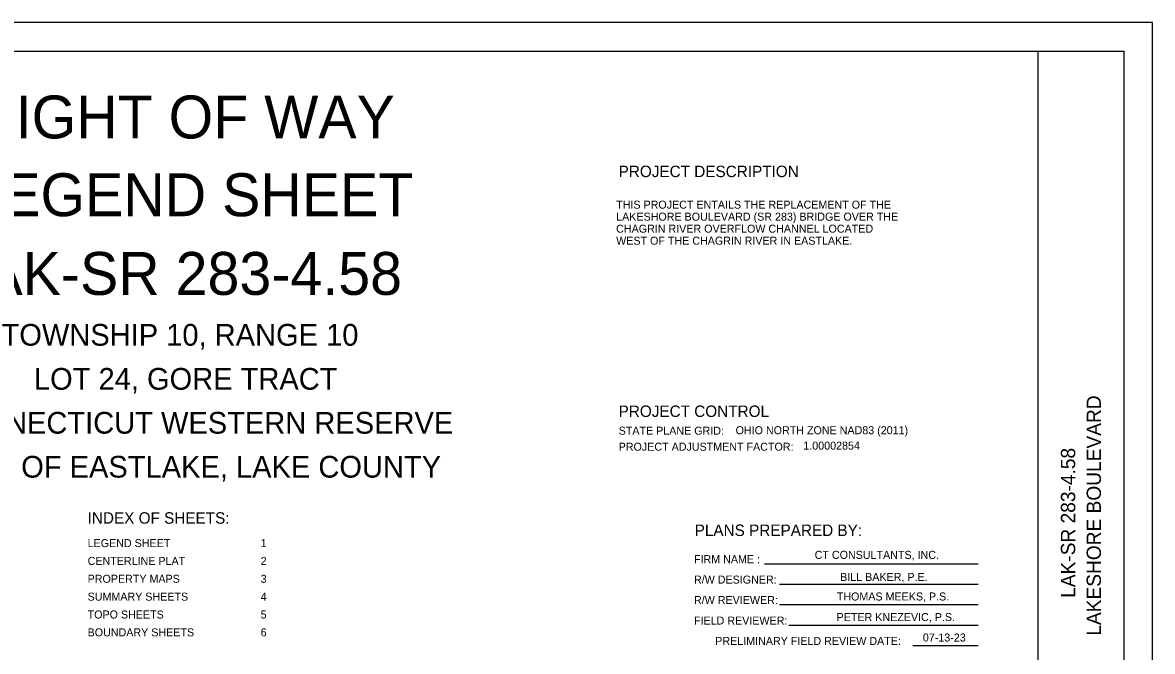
# Model space of a CAD drawing. Extents: x 0 to 34, y 0 to 22.
# Drawn here: x 14.24 to 34, y 11.01 to 22 of the extents above; entities that cross this region are included whole.
import ezdxf

# ---------------------------------------------------------------- set-up
doc = ezdxf.new("R2010")
doc.units = 0
for name, color, linetype in [('Default', 7, 'Continuous'), ('SH_Border', 7, 'Continuous'), ('SH_Cut_Line', 7, 'Continuous'), ('SH_Data', 7, 'Continuous'), ('SH_Text', 7, 'Continuous'), ('SN_P_Text', 7, 'Continuous')]:
    doc.layers.add(name, color=color, linetype=linetype)

msp = doc.modelspace()

# ---------------------------------------------------------------- linework, layer by layer
at = {"layer": 'Default'}
msp.add_line((1.5, 21.5), (32, 21.5), dxfattribs=at)
at = {"layer": 'SH_Border'}
msp.add_line((32, 0.5), (32, 21.5), dxfattribs=at)
msp.add_lwpolyline([(1.5, 21.5), (33.5, 21.5), (33.5, 0.5), (1.5, 0.5)], close=True, dxfattribs=at)
at = {"layer": 'SH_Cut_Line'}
msp.add_lwpolyline([(0, 0), (34, 0), (34, 22), (0, 22)], close=True, dxfattribs=at)
at = {"layer": 'SH_Text'}
for p, q in [((27.216, 12.544), (30.953, 12.544)), ((27.48, 12.187), (30.953, 12.187)), ((27.48, 11.83), (30.953, 11.83)), ((27.644, 11.473), (30.953, 11.473)), ((29.808, 11.115), (30.953, 11.115))]:
    msp.add_line(p, q, dxfattribs=at)

# ---------------------------------------------------------------- texts
at = {"layer": 'SH_Data'}
for s, height, p in [('RIGHT OF WAY', 0.75, (13.399, 19.976)), ('LEGEND SHEET', 0.75, (13.33, 18.617)), ('LAK-SR 283-4.58', 0.75, (13.018, 17.242)), ('TOWNSHIP 10, RANGE 10', 0.38, (13.876, 16.354)), ('LOT 24, GORE TRACT', 0.38, (14.442, 15.585)), ('CONNECTICUT WESTERN RESERVE', 0.38, (12.825, 14.817)), ('CITY OF EASTLAKE, LAKE COUNTY', 0.38, (12.921, 14.049)), ('INDEX OF SHEETS:', 0.2, (15.381, 13.244)), ('LEGEND SHEET', 0.14, (15.381, 12.835)), ('1', 0.14, (18.407, 12.835)), ('CENTERLINE PLAT', 0.14, (15.381, 12.523)), ('2', 0.14, (18.407, 12.523)), ('PROPERTY MAPS', 0.14, (15.381, 12.211)), ('3', 0.14, (18.407, 12.211)), ('SUMMARY SHEETS', 0.14, (15.381, 11.899)), ('4', 0.14, (18.407, 11.899)), ('TOPO SHEETS', 0.14, (15.381, 11.587)), ('5', 0.14, (18.407, 11.587)), ('BOUNDARY SHEETS', 0.14, (15.381, 11.275)), ('6', 0.14, (18.407, 11.275))]:
    msp.add_text(s, height=height, dxfattribs=at).set_placement(p)
for s, p in [('LAKESHORE BOULEVARD', (33.1, 11.287)), ('LAK-SR 283-4.58', (32.65, 11.948))]:
    msp.add_text(s, height=0.25, rotation=90, dxfattribs=at).set_placement(p)
at = {"layer": 'SH_Text'}
for s, height, p in [('THIS PROJECT ENTAILS THE REPLACEMENT OF THE', 0.14, (24.623, 18.749)), ('LAKESHORE BOULEVARD (SR 283) BRIDGE OVER THE ', 0.14, (24.623, 18.539)), ('CHAGRIN RIVER OVERFLOW CHANNEL LOCATED ', 0.14, (24.623, 18.329)), ('WEST OF THE CHAGRIN RIVER IN EASTLAKE.', 0.14, (24.623, 18.119)), ('PROJECT CONTROL', 0.2, (24.666, 15.109)), ('STATE PLANE GRID:', 0.14, (24.667, 14.799)), (' OHIO NORTH ZONE NAD83 (2011)', 0.14, (26.66, 14.807)), ('PROJECT ADJUSTMENT FACTOR:', 0.14, (24.667, 14.519)), ('1.00002854', 0.14, (27.896, 14.538)), ('PLANS PREPARED BY:', 0.2, (25.996, 13.029)), ('FIRM NAME :', 0.14, (25.984, 12.554)), ('R/W DESIGNER:', 0.14, (25.984, 12.197)), ('R/W REVIEWER:', 0.14, (25.984, 11.84)), ('FIELD REVIEWER:', 0.14, (25.984, 11.482)), ('PRELIMINARY FIELD REVIEW DATE:', 0.14, (26.356, 11.125))]:
    msp.add_text(s, height=height, dxfattribs=at).set_placement(p)
at = {"layer": 'SN_P_Text'}
for s, height, p in [('PROJECT DESCRIPTION', 0.2, (24.666, 19.3)), ('CT CONSULTANTS, INC.', 0.14, (28.094, 12.629)), ('BILL BAKER, P.E.', 0.14, (28.54, 12.243)), ('THOMAS MEEKS, P.S.', 0.14, (28.481, 11.902)), ('PETER KNEZEVIC, P.S.', 0.14, (28.478, 11.542)), ('07-13-23', 0.14, (29.986, 11.185))]:
    msp.add_text(s, height=height, dxfattribs=at).set_placement(p)

doc.saveas('drawing.dxf')
